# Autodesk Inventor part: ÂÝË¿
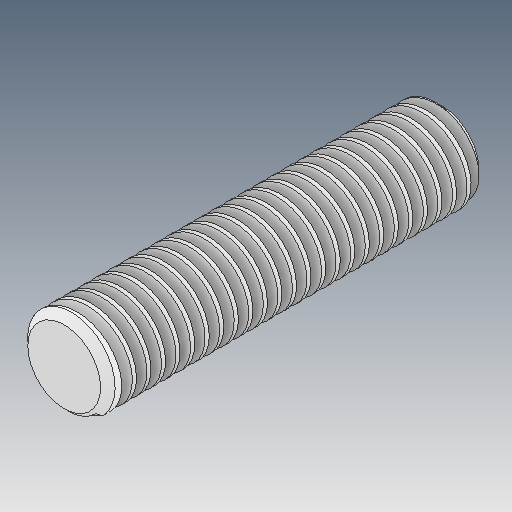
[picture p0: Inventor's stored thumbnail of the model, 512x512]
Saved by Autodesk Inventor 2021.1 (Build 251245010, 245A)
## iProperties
Created: 2021-06
Part Number: ÂÝË¿
Material: Ogólny
Document SubType Name: Modeling
Designer: user
Density: 1 g/cm^3
Appearance: Domyślna
Author: user
Revision Number: ÈÎºÎ
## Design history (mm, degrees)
feature "ÇÐ³ý-É¨Ãè1"
node "Bryła1"
